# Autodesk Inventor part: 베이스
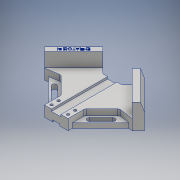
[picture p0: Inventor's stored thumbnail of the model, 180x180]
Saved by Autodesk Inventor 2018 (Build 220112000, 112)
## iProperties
Created: 2020-05
Part Number: 베이스
Material: 알루미늄 6061
Document SubType Name: Modeling
Designer: Administrator
Density: 2.7 g/cm^3
Appearance: 알루미늄 - 평지
Author: Administrator
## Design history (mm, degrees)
sketch "스케치1"
  geometry: L1 (0, 84.853)-(-84.853, 0); L2 (-84.853, 0)-(0, -84.853); L3 (0, -84.853)-(84.853, 0); L4 (84.853, 0)-(0, 84.853); 1 further point
  constraints: 8 end point, 2 horizontal alignment, 2 vertical alignment, 1 point on line
  dimensions: "d0" = 120 distance of L1.start L1.end; "d1" = 120 distance of L1.end L2.end; "d2" = 120 distance of L2.end L3.end; "d3" = 120 distance of L3.end L4.end; "d4" = 90 deg angle of L2 L1
extrude "돌출1" new body sketch "스케치1" stored distance "d5" = 42; taper "d6" = 0 deg
node "스케치2"
sketch "스케치3"
  geometry: L1 (0, 84.853)-(-84.853, 0) reference; L2 (84.853, 0)-(0, 84.853) reference; L3 (-74.246, -10.607)-(0, 63.64); L4 (0, 63.64)-(74.246, -10.607); L5 (-84.853, 0)-(0, -84.853) reference; L6 (0, -84.853)-(84.853, 0) reference; 1 further point
  constraints: 4 end point, 1 other
  dimensions: "d7" = 15 distance between parallel lines of L1 L3
extrude "돌출2" cut sketch "스케치3" distance "d8" = 24; taper "d9" = 0 deg
sketch "스케치4"
  geometry: L1 (-16.005, 30.147)-(-35.355, 49.497); L2 (0, 84.853)-(-84.853, 0) reference; L3 (35.355, 49.497)-(16.005, 30.147); L4 (84.853, 0)-(0, 84.853) reference; L5 (0, -84.853)-(-84.853, 0) reference; L6 (0, 30.147)-(16.005, 30.147); L7 (16.005, 30.147)-(-16.005, 30.147); 1 further point
  constraints: 8 end point, 1 parallel
  dimensions: "d11" = 50 distance between parallel lines of L2 L3; "d13" = 115 distance of L5.start L6.start
extrude "돌출3" cut sketch "스케치4" distance "d14" = 42; taper "d15" = 0 deg
sketch "스케치5"
  geometry: L1 (0, -84.853)-(-74.246, -10.607) reference; L2 (-20, -36.569)-(-49.497, -7.071); L3 (-35.355, 49.497)-(-84.853, 0) reference; L4 (-49.497, -7.071)-(-74.246, -10.607); L5 (-20, -64.853)-(-20, -36.569); 1 further point
  constraints: 6 end point, 1 parallel, 1 point on line, 1 vertical
  dimensions: "d16" = 20 distance between parallel lines of L1 L2
extrude "돌출4" cut sketch "스케치5" distance "d19" = 10; taper "d20" = 0 deg
sketch "스케치6"
  geometry: L1 (-20, -64.853)-(-74.246, -10.607) reference; L2 (-20, -57.782)-(-68.059, -9.723); L3 (-74.246, -10.607)-(-49.497, -7.071) reference; L4 (-20, -36.569)-(-20, -64.853) reference; 1 further point
  constraints: 2 end point, 2 point on line, 1 parallel
  dimensions: "d21" = 5 distance between parallel lines of L1 L2
extrude "돌출5" cut sketch "스케치6" distance "d22" = 10; taper "d23" = 0 deg
sketch "스케치7"
  geometry: L1 (0, -84.853)-(-20, -64.853) reference; L2 (-20, -64.853)-(20, -64.853); L3 (74.246, -10.607)-(0, -84.853) reference; 1 further point
  constraints: 2 end point, 1 horizontal, 1 point on line
extrude "돌출6" cut sketch "스케치7" distance "d24" = 42; taper "d25" = 0 deg
sketch "스케치8"
  geometry: L1 (-68.059, -9.723)-(-20, -57.782) reference; L2 (-74.246, -10.607)-(-20, -64.853); L3 (-35.355, 49.497)-(-84.853, 0) reference; L4 (-52.326, -21.213)-(-32.527, -41.012); L5 (-46.669, -15.556)-(-26.87, -35.355); A1 r 4 centre (-49.497, -18.385) between (-46.669, -15.556) and (-52.326, -21.213); A2 r 4 centre (-29.698, -38.184) between (-32.527, -41.012) and (-26.87, -35.355); 1 further point
  constraints: 6 end point, 4 point on circle, 2 centre point
  dimensions: "d29" = 8 diameter of A1; "d30" = 8 diameter of A2
extrude "돌출7" cut sketch "스케치8" distance "d31" = 42; taper "d32" = 0 deg
sketch "스케치9"
  geometry: L1 (-20, -64.853)-(20, -64.853) reference; C1 r 2.25 at (-14, -46.853); C2 r 2.25 at (-14, -58.853); C3 r 2.25 at (14, -46.853); C4 r 2.25 at (14, -58.853); 1 further point
  constraints: 4 centre point
  dimensions: "d37" = 4.5 diameter of C1; "d38" = 4.5 diameter of C2; "d39" = 4.5 diameter of C3; "d40" = 4.5 diameter of C4
extrude "돌출8" cut sketch "스케치9" distance "d41" = 42; taper "d42" = 0 deg
sketch "스케치10"
  geometry: L1 (-8, 30.147)-(-8, -65.204); L2 (8, 30.147)-(8, -65.204); L3 (-8, 30.147)-(8, 30.147); L4 (16.005, 30.147)-(-16.005, 30.147) reference; L5 (-8, -65.204)-(8, -65.204); L6 (-20, -64.853)-(20, -64.853) reference; 1 further point
  constraints: 8 end point, 1 collinear, 1 parallel
extrude "돌출9" cut sketch "스케치10" distance "d45" = 3.5; taper "d46" = 0 deg
sketch "스케치11"
  geometry: L1 (40, 0)-(0, 0) reference; L2 (14, 0)-(14, 3); L3 (26, 0)-(26, 3); L4 (14, 0)-(26, 0); L5 (3.995, 0)-(36.005, 0) reference; L6 (20, 3)-(14, 3); L7 (26, 3)-(20, 3); 1 further point
  constraints: 10 end point, 2 collinear, 1 parallel, 1 perpendicular, 1 point on line
extrude "돌출10" cut sketch "스케치11" distance "d50" = 151; taper "d51" = 0 deg
sketch "스케치12"
  geometry: C1 r 2.25 at (14, -58.853) reference; C2 r 4 at (14, -58.853); C3 r 2.25 at (14, -46.853) reference; C4 r 4 at (14, -46.853); C5 r 2.25 at (-14, -58.853) reference; C6 r 4 at (-14, -58.853); C7 r 2.25 at (-14, -46.853) reference; C8 r 4 at (-14, -46.853); 1 further point
  constraints: 4 centre point, 4 coincident
  dimensions: "d52" = 8 diameter of C2; "d53" = 8 diameter of C4; "d54" = 8 diameter of C6; "d55" = 8 diameter of C8
extrude "돌출11" cut sketch "스케치12" distance "d56" = 10; taper "d57" = 0 deg
fillet "모깎기1" dims "d58" = 5
sketch "스케치13"
  geometry: L1 (0, 15)-(-5, 0); L2 (-5, 0)-(0, 0); L3 (0, 0)-(0, 15); 1 further point
  constraints: 6 end point, 1 perpendicular
extrude "돌출12" cut sketch "스케치13" distance "d61" = 100; taper "d62" = 0 deg
sketch "스케치14"
  geometry: L1 (-24.749, 38.891)-(-74.246, -10.607); L2 (-74.246, -10.607)-(-81.317, -3.536); L3 (-81.317, -3.536)-(-31.82, 45.962); L4 (-31.82, 45.962)-(-24.749, 38.891); L5 (-24.749, 38.891)-(-31.82, 45.962) reference; L6 (-81.317, -3.536)-(-74.246, -10.607) reference; 1 further point
  constraints: 2 coincident, 2 other
feature "엠보싱1" sketch "스케치14" dims "d0" = 120, "d1" = 120, "d2" = 120, "d3" = 120, "d4" = 90 deg, "d63" = 0.5, "d64" = 0
node "솔리드1"
mirror "미러1"
mirror "미러2"
